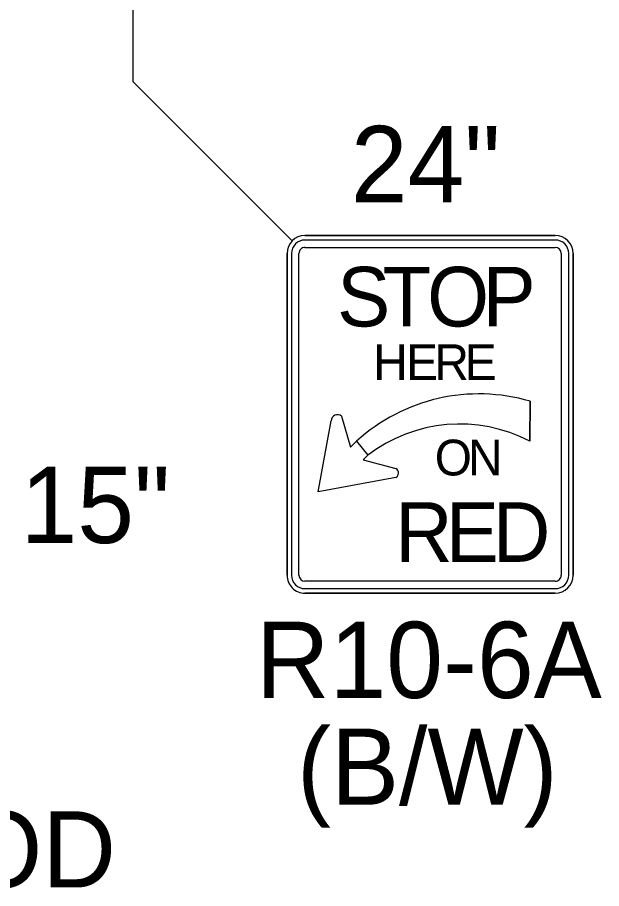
# Model space of a CAD drawing. Extents: x 99982 to 100176, y 99905 to 100011.
# Drawn here: x 100049.749 to 100050.3, y 99915.077 to 99915.9 of the extents above; entities that cross this region are included whole.
import ezdxf

# ---------------------------------------------------------------- set-up
doc = ezdxf.new("R2010")
doc.units = 0
doc.layers.add('TR_SN_ConstructionSigns', color=7, linetype='Continuous')
doc.layers.add('TR_WZ_WorkZoneDetails', color=7, linetype='Continuous')

msp = doc.modelspace()

# ---------------------------------------------------------------- linework, layer by layer
at = {"layer": 'TR_SN_ConstructionSigns'}
for p, q in [((100050.25623, 99915.69376), (100050.01998, 99915.69376)), ((100050.01998, 99915.69376), (100050.25623, 99915.69376)), ((100050.25623, 99915.69376), (100050.01998, 99915.69376)), ((100050.01998, 99915.69376), (100050.25623, 99915.69376)), ((100050.25623, 99915.68954), (100050.01998, 99915.68954)), ((100050.01998, 99915.68251), (100050.25623, 99915.68251)), ((100050.0031, 99915.67689), (100050.0031, 99915.37314)), ((100050.0031, 99915.37314), (100050.0031, 99915.67689)), ((100050.0031, 99915.67689), (100050.0031, 99915.37314)), ((100050.0031, 99915.37314), (100050.0031, 99915.67689)), ((100050.00732, 99915.67689), (100050.00732, 99915.37314)), ((100050.01435, 99915.37314), (100050.01435, 99915.67689)), ((100050.26185, 99915.67689), (100050.26185, 99915.37314)), ((100050.26888, 99915.37314), (100050.26888, 99915.67689)), ((100050.2731, 99915.37314), (100050.2731, 99915.67689)), ((100050.2731, 99915.67689), (100050.2731, 99915.37314)), ((100050.2731, 99915.37314), (100050.2731, 99915.67689)), ((100050.2731, 99915.67689), (100050.2731, 99915.37314)), ((100050.23257, 99915.53736), (100050.23226, 99915.49959)), ((100050.23226, 99915.49959), (100050.23257, 99915.53736)), ((100050.05461, 99915.52323), (100050.0631, 99915.49406)), ((100050.03263, 99915.45189), (100050.04487, 99915.51888)), ((100050.0631, 99915.49406), (100050.06879, 99915.49976)), ((100050.06879, 99915.49976), (100050.07932, 99915.48635)), ((100050.06879, 99915.49976), (100050.07932, 99915.48635)), ((100050.07932, 99915.48635), (100050.07504, 99915.48208)), ((100050.07504, 99915.48208), (100050.10582, 99915.4738)), ((100050.10566, 99915.46545), (100050.03263, 99915.45189)), ((100050.25623, 99915.36751), (100050.01998, 99915.36751)), ((100050.01998, 99915.36048), (100050.25623, 99915.36048)), ((100050.01998, 99915.35626), (100050.25623, 99915.35626)), ((100050.25623, 99915.35626), (100050.01998, 99915.35626)), ((100050.01998, 99915.35626), (100050.25623, 99915.35626)), ((100050.25623, 99915.35626), (100050.01998, 99915.35626))]:
    msp.add_line(p, q, dxfattribs=at)
for centre, radius, start, end in [((100050.01998, 99915.67689), 0.01688, 90, 180), ((100050.01998, 99915.67689), 0.01688, 90, 180), ((100050.01998, 99915.67689), 0.01688, 90, 180), ((100050.01998, 99915.67689), 0.01688, 90, 180), ((100050.01998, 99915.67689), 0.01266, 90, 180.00001), ((100050.25623, 99915.67689), 0.01688, 0, 90), ((100050.25623, 99915.67689), 0.01688, 0, 90), ((100050.25623, 99915.67689), 0.01688, 0, 90), ((100050.25623, 99915.67689), 0.01688, 0, 90), ((100050.25623, 99915.67689), 0.01266, 0, 90), ((100050.01998, 99915.67689), 0.00562, 90, 180.00001), ((100050.25623, 99915.67689), 0.00562, 0, 90), ((100050.1842, 99915.37254), 0.17177, 73.6434, 132.21315), ((100050.1842, 99915.37254), 0.17177, 73.6434, 132.21315), ((100050.16616, 99915.37308), 0.14273, 62.4149, 127.4769), ((100050.16616, 99915.37308), 0.14273, 62.4149, 127.4769), ((100050.01998, 99915.37314), 0.01688, 180, 270.00001), ((100050.01998, 99915.37314), 0.01688, 180, 270.00001), ((100050.01998, 99915.37314), 0.01688, 180, 270.00001), ((100050.01998, 99915.37314), 0.01688, 180, 270.00001), ((100050.01998, 99915.37314), 0.01266, 180.00001, 270), ((100050.01998, 99915.37314), 0.00562, 180.00001, 270), ((100050.25623, 99915.37314), 0.01688, 270.00001, 0.00001), ((100050.25623, 99915.37314), 0.01688, 270.00001, 0.00001), ((100050.25623, 99915.37314), 0.01688, 270.00001, 0.00001), ((100050.25623, 99915.37314), 0.01266, 270, 0.00001), ((100050.25623, 99915.37314), 0.00562, 270, 0.00001), ((100050.25623, 99915.37314), 0.01688, 270.00001, 0.00001)]:
    msp.add_arc(centre, radius, start, end, dxfattribs=at)
for centre, major_axis, ratio, start_param, end_param in [((100050.05069, 99915.51896), (-0.00583, -0.00008), 0.989437, 3.962549, 6.283185), ((100050.10367, 99915.46967), (-0.00414, 0.00215), 0.999053, 2.490568, 4.712389)]:
    msp.add_ellipse(centre, major_axis=major_axis, ratio=ratio, start_param=start_param, end_param=end_param, dxfattribs=at)
at = {"layer": 'TR_WZ_WorkZoneDetails'}
for p, q in [((100049.85755, 99916.33467), (100049.85755, 99915.83931)), ((100049.85755, 99915.83931), (100050.00804, 99915.68882))]:
    msp.add_line(p, q, dxfattribs=at)

# ---------------------------------------------------------------- texts
at = {"layer": 'TR_SN_ConstructionSigns'}
for s, p in [('24"', (100050.06333, 99915.72526)), ('15"', (100049.75162, 99915.40354)), ('R10-6A', (100049.97367, 99915.25726)), ('(B/W)', (100050.01252, 99915.15646)), ('R10-24 MOD', (100049.27452, 99915.07841))]:
    msp.add_text(s, height=0.072, rotation=360, dxfattribs=at).set_placement(p)
for s, height, p in [('S', 0.05625, (100050.05035, 99915.60798)), ('T', 0.05625, (100050.0931, 99915.60798)), ('O', 0.05625, (100050.13529, 99915.60798)), ('P', 0.05625, (100050.1876, 99915.60798)), ('H', 0.03375, (100050.08444, 99915.55736)), ('E', 0.03375, (100050.11549, 99915.55736)), ('R', 0.03375, (100050.14215, 99915.55736)), ('E', 0.03375, (100050.17084, 99915.55736)), ('O', 0.03375, (100050.14249, 99915.46736)), ('N', 0.03375, (100050.17387, 99915.46736)), ('R', 0.05625, (100050.10504, 99915.38579)), ('E', 0.05625, (100050.15286, 99915.38579)), ('D', 0.05625, (100050.19729, 99915.38579))]:
    msp.add_text(s, height=height, dxfattribs=at).set_placement(p)

doc.saveas('drawing.dxf')
